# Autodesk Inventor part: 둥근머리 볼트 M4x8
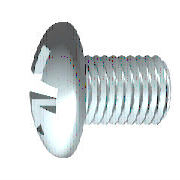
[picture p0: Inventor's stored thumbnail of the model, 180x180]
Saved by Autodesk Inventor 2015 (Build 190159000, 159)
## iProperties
Created: 2012-02
Part Number: 둥근머리 볼트 M4x8
Material: 강철, 연강
Description: 십자 오목 머리 나사
Document SubType Name: Modeling
Standard: KS B 1023
Designer: mduedu
Standards Organization: KS
Language: ko-KR
Size Designation: A  M 4 x 8 - H
Categories: <MemberInstance><Categories><Category DisplayName="조임쇠" InternalName="e4da775c-781d-43d5-af7c-5136215cf5a6" Mnemonic="FSTN"><Category DisplayName="볼트" InternalN
Density: 7.85 g/cm^3
Appearance: 노란색
Mass: 1.61724 g
Surface Area: 2.62078 cm^2
Volume: 0.206017 cm^3
IsCustomPart: 1
Author: mduedu
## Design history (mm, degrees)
body "Solid1"
workplane "Work Plane3"
sketch "스케치2"
  geometry: L1 (-5.374, 0)-(5.374, 0) reference; L2 (0, -5.374)-(0, 5.374) reference; L3 (0, 2.3)-(0, 0); L4 (0, 0)-(2.3, 0); L5 (0, 0)-(2.714, 2.714); L6 (0.311, 2.279)-(0.392, 0.703); L7 (2.279, 0.311)-(0.703, 0.392); L8 (0.311, -2.279)-(0.392, -0.703); L9 (2.279, -0.311)-(0.703, -0.392); L10 (-0.311, 2.279)-(-0.392, 0.703); L11 (-2.279, 0.311)-(-0.703, 0.392); L12 (-2.279, -0.311)-(-0.703, -0.392); L13 (-0.311, -2.279)-(-0.392, -0.703); A1 r 0.69 centre (0, 0) between (0.69, 0) and (0, 0.69); A2 r 2.3 centre (0, 0) between (2.3, 0) and (2.279, 0.311); A3 r 2.3 centre (0, 0) between (0.311, 2.279) and (0, 2.3); A4 r 2.3 centre (0, 0) between (2.279, 0.311) and (0.311, 2.279); A5 r 2.3 centre (0, 0) between (0, -2.3) and (0.311, -2.279); A6 r 2.3 centre (0, 0) between (0.311, -2.279) and (2.279, -0.311); A7 r 2.3 centre (0, 0) between (2.279, -0.311) and (2.3, 0); A8 r 2.3 centre (0, 0) between (-2.279, 0.311) and (-2.3, 0); A9 r 2.3 centre (0, 0) between (-0.311, 2.279) and (-2.279, 0.311); A10 r 2.3 centre (0, 0) between (0, 2.3) and (-0.311, 2.279); A11 r 2.3 centre (0, 0) between (-2.3, 0) and (-2.279, -0.311); A12 r 2.3 centre (0, 0) between (-2.279, -0.311) and (-0.311, -2.279); A13 r 2.3 centre (0, 0) between (-0.311, -2.279) and (0, -2.3); A14 r 0.805 centre (0, 0) between (0.805, 0) and (0, 0.805); A15 r 0.328 centre (0.72, 0.72) between (0.392, 0.703) and (0.703, 0.392); A16 r 0.328 centre (0.72, -0.72) between (0.703, -0.392) and (0.392, -0.703); A17 r 0.328 centre (-0.72, 0.72) between (-0.703, 0.392) and (-0.392, 0.703); A18 r 0.328 centre (-0.72, -0.72) between (-0.392, -0.703) and (-0.703, -0.392); 1 further point
  constraints: 38 point on circle, 22 end point, 19 symmetric about line, 18 centre point, 4 coincident, 3 collinear, 3 point on line, 3 tangent, 1 perpendicular, 21 other
  dimensions: "d4" = 45 deg angle of L5 L4; "d5" = 1.38 diameter of A1 (= 0.3 x SDM); "d6" = 4.6 diameter of A4 (= SDM); "d7" = 0.3115 distance from line of L6.start L3 (= 0.5 x SBR); "d14" = 1.61 diameter of A14 (= 0.35 x SDM)
extrude "슬롯" join sketch "스케치2" taper "d15" = 5 deg; stored distance "d54" = 10
revolve "절단부" stored, may be unused: angle "d56" = 90 deg
revolve "본체" stored, may be unused: angle "d18" = 90 deg
workplane "Work Plane1"
sketch "스케치1"
  geometry: L1 (8, 0)-(8, 2); L2 (8, 2)-(1.4, 2); L3 (3.962, 5.08)-(3.962, 5.08); L4 (-3.1, 0)-(-3.1, 3.729); L5 (-2.744, 2.122)-(-1.498, 1.501); L6 (-1.498, 1.501)-(-0.7, 0); L7 (-0.7, 0)-(8, 0); L8 (-5.687, 0)-(10.281, 0) reference; L9 (0, -1.016)-(0, 6.096) reference; L10 (-2.744, 2.122)-(-3.1, 2.3); L11 (-1.846, 3.839)-(-3.1, 3.729); L12 (-1.846, 3.839)-(0, 4); L13 (0, 4)-(0, 1.785); L14 (0, 1.785)-(0.971, 1.785); L15 (0.971, 1.785)-(1.4, 2); L16 (1.4, 2)-(0, 2); A1 r 6.5 centre (3.4, 0) between (-1.846, 3.839) and (-3.1, 0)
  constraints: 28 end point, 5 point on line, 4 collinear, 4 point on circle, 3 parallel, 2 perpendicular, 1 centre point, 1 horizontal, 1 tangent
  dimensions: "d1" = 4 diameter of L2 L7 (= GD); "d2" = 2.4 distance from line of L6.end L4 (= STI); "d11" = 4.6 diameter of L10.end L7 (= SDM); "d12" = 62 deg angle of L6 L7; "d13" = 26.5 deg angle of L5 L7; "d17" = 8 diameter of L12.end L7 (= KOD); "d19" = 5 deg angle of L12 L7 (= KEWI); "d20" = 3.1 distance between parallel lines of L4 L13 (= KOH); "d21" = 6.5 radius of A1 (= KR); "d23" = 3.5705 diameter of L14 L7 (= BDM); "d24" = 6.6 distance of L1.end L2.end (= GEL); "d25" = 0.42941 horizontal distance of L14.end L2.end (= GAL); "d28" = 8 distance between parallel lines of L1 L13 (= NLG)
fillet "모깎기1" dims "d29" = 1.6 (= RR)
fillet "모깎기2" dims "d16" = 0.1246 (= 0.2 x SBR)
feature "스레드" dims "d8" = 6.6 (= GEL), "d9" = 0
chamfer "모따기1" distance "d26" = 0.42941 (= -0.5 x SPD + 0.5 x GD); stored, may be unused: second distance "d27" = 0.42952 (computed from GUL), angle "d78" = 45 deg
other parameters: "GD" = 4 (= NND) [user parameter; used in 2 equation terms], "NLG" = 8 [user parameter; used in 1 equation term], "GEL" = 6.6 [user parameter; used in 2 equation terms], "KOD" = 8 [user parameter; used in 1 equation term], "KOH" = 3.1 [user parameter; used in 2 equation terms], "SDM" = 4.6 [user parameter; used in 4 equation terms], "STI" = 2.4 [user parameter; used in 1 equation term], "SBR" = 0.623 [user parameter; used in 2 equation terms], "GAL" = 0.42941 (= 0.61345 x PTC) [user parameter; used in 1 equation term], "SPD" = 3.14117 (= NND - 1.2269 x PTC) [user parameter; used in 1 equation term], "KEWI" = 5 deg [user parameter; used in 1 equation term], "d3" = -3.1 (= -KOH), "d10" = 0, "KR" = 6.5 [user parameter; used in 1 equation term], "BDM" = 3.5705 [user parameter; used in 1 equation term], "GUL" = 0.42941 (= 0.61345 x PTC) [user parameter; used in 1 equation term], "RR" = 1.6 [user parameter; used in 1 equation term], "d79" = 0, "d80" = 0, "PTC" = 0.7 [user parameter; used in 5 equation terms], "THREADDIA" = 4 [user parameter; used in 1 equation term], "TOA" = 30 deg [user parameter], "TPU" = 14.28571 (computed from PTC) [user parameter], "NND" = 4 [user parameter; used in 2 equation terms], "GD1" = 3.14117 (= THREADDIA - 1.2269 x PTC) [user parameter]
